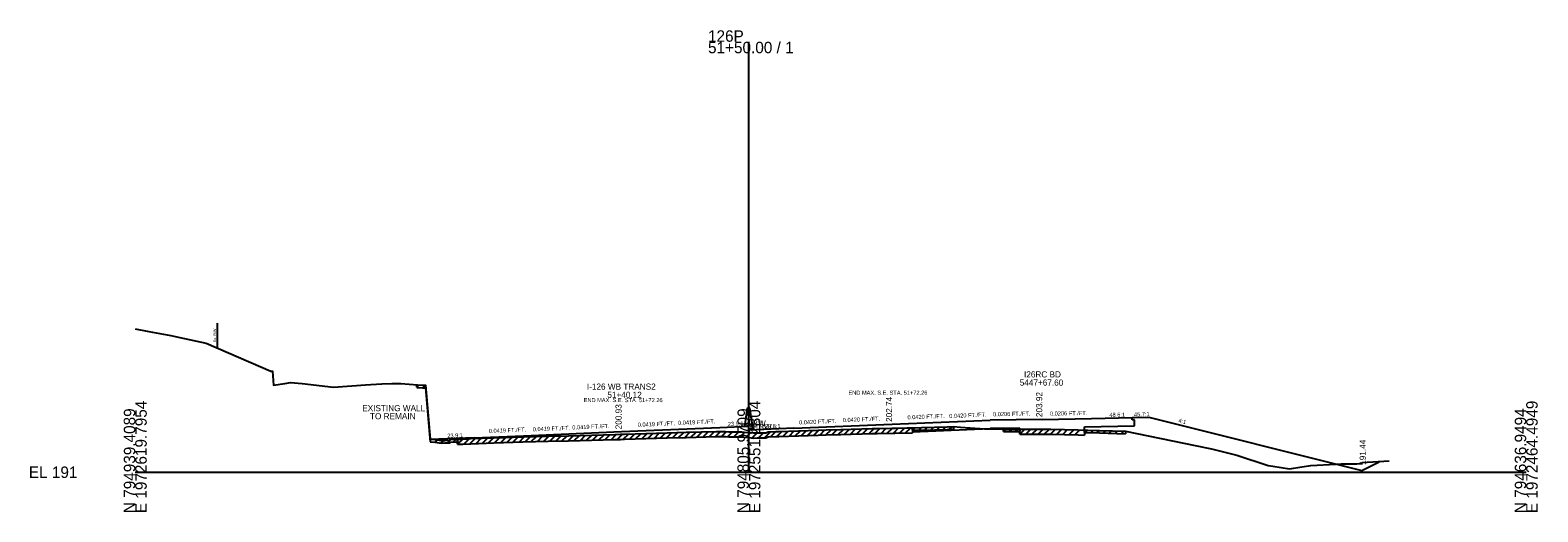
# Model space of a CAD drawing. Extents: x -161 to 1970889, y -4362 to 797231.
# Drawn here: x 1974.3 to 2342.8, y 3990.3 to 4108.1 of the extents above; entities that cross this region are included whole.
import ezdxf

# ---------------------------------------------------------------- set-up
doc = ezdxf.new("R2010")
doc.units = 0
for name, color, linetype in [('RD_GPK_XS_Cell', 7, 'Continuous'), ('RD_XS_Base', 7, 'Continuous'), ('RD_XS_EarthShd', 7, 'Continuous'), ('RD_XS_ExGround', 7, 'Continuous'), ('RD_XS_ExPaveRet', 7, 'Continuous'), ('RD_XS_ExRW', 7, 'Continuous'), ('RD_XS_MedBWall', 7, 'Continuous'), ('RD_XS_Misc_Line', 7, 'Continuous'), ('RD_XS_Pave', 7, 'Continuous'), ('RD_XS_PaveOvlay', 7, 'Continuous'), ('RD_XS_PaveShd', 7, 'Continuous'), ('RD_XS_TieSlope', 7, 'Continuous'), ('RD_XS_TX_Elev_EX', 7, 'Continuous'), ('RD_XS_TX_Elev_PR', 7, 'Continuous'), ('RD_XS_TX_Misc', 7, 'Continuous'), ('RD_XS_TX_MkPT', 7, 'Continuous'), ('RD_XS_TX_Notes', 7, 'Continuous'), ('RD_XS_TX_Profile', 7, 'Continuous'), ('RD_XS_TX_ShdSlope', 7, 'Continuous'), ('RD_XS_TX_Slope', 7, 'Continuous'), ('RD_XS_TX_Station', 7, 'Continuous')]:
    doc.layers.add(name, color=color, linetype=linetype)

msp = doc.modelspace()

# ---------------------------------------------------------------- linework, layer by layer
at = {"layer": 'RD_GPK_XS_Cell'}
for p, q in [((2150, 4000), (2150, 4105.24)), ((2000, 4000), (2150, 4000)), ((2150, 4000), (2340, 4000))]:
    msp.add_line(p, q, dxfattribs=at)
at = {"layer": 'RD_XS_Base'}
for p, q in [((2243.71, 4012.81), (2243.71, 4013.37)), ((2190.02, 4009.91), (2209, 4010.71)), ((2216.19, 4010.8), (2209, 4010.71)), ((2232.05, 4011.09), (2244.21, 4011.34)), ((2244.21, 4012.82), (2243.71, 4012.81)), ((2244.21, 4011.34), (2244.21, 4012.82))]:
    msp.add_line(p, q, dxfattribs=at)
at = {"layer": 'RD_XS_EarthShd'}
msp.add_line((2243.71, 4013.37), (2247.72, 4013.46), dxfattribs=at)
at = {"layer": 'RD_XS_ExGround'}
msp.add_line((2306.53, 4002.71), (2299.85, 4002.33), dxfattribs=at)
msp.add_lwpolyline([(2000, 4035.08), (2003.32, 4034.41), (2008.67, 4033.4), (2010.9, 4032.92), (2017.34, 4031.59), (2030.67, 4025.76), (2033.16, 4024.69), (2033.54, 4024.69), (2033.77, 4021.28), (2036.55, 4021.69), (2037.94, 4021.9), (2040.76, 4021.65), (2048.47, 4020.83), (2056.26, 4021.35), (2060.27, 4021.61), (2062.73, 4021.71), (2064.88, 4021.73), (2068.98, 4021.37), (2070.21, 4021.28), (2070.97, 4021.28), (2072.09, 4008.08), (2073.25, 4007.96), (2074.87, 4007.77), (2075.65, 4007.79), (2076.87, 4007.82), (2077.14, 4008), (2080.07, 4008.12), (2082.04, 4008.21), (2087.62, 4008.41), (2094.77, 4008.67), (2100.95, 4008.81), (2105.87, 4008.93), (2117.23, 4009.23), (2118.59, 4009.27), (2119.62, 4009.29), (2130.04, 4009.62), (2134.69, 4009.76), (2141.98, 4009.97), (2143.34, 4009.98), (2144.27, 4009.97), (2145.07, 4009.86), (2147.8, 4009.89), (2148.3, 4009.9), (2148.81, 4009.83), (2150, 4009.71), (2151.13, 4009.6), (2151.99, 4009.62), (2154.17, 4009.65), (2154.72, 4009.86), (2156.54, 4009.95), (2157.27, 4009.99), (2166.96, 4010.29), (2168.88, 4010.35), (2172.45, 4010.46), (2180.12, 4010.69), (2181.38, 4010.72), (2192.19, 4010.94), (2198.49, 4011.1), (2200.02, 4011.14), (2201.69, 4011.03), (2207.56, 4010.59), (2210.13, 4010.6), (2212.19, 4010.55), (2214.94, 4010.55), (2215.95, 4010.55), (2217.48, 4010.55), (2223.83, 4010.53), (2230.49, 4010.36), (2232.85, 4010.3), (2235.72, 4010.22), (2242.06, 4010.04), (2259.1, 4006.5), (2263.06, 4005.68), (2269.24, 4004.18), (2276.94, 4001.63), (2278.08, 4001.46), (2282.15, 4000.83), (2285.18, 4001.3), (2287.35, 4001.64), (2293.43, 4001.93), (2294.8, 4002.02), (2298.57, 4002.07), (2300, 4002.09)], dxfattribs=at)
at = {"layer": 'RD_XS_ExPaveRet'}
for p, q in [((2068.8, 4020.76), (2068.8, 4021.38)), ((2068.8, 4020.76), (2068.98, 4020.74)), ((2068.98, 4020.74), (2070.21, 4020.66)), ((2070.21, 4020.66), (2070.97, 4020.66)), ((2070.97, 4020.66), (2072.09, 4007.46)), ((2181.38, 4009.47), (2190.02, 4009.64)), ((2190.02, 4010.89), (2190.02, 4009.64)), ((2190.02, 4010.27), (2190.02, 4010.89)), ((2190.02, 4010.27), (2192.19, 4010.31)), ((2192.19, 4010.31), (2198.49, 4010.48)), ((2198.49, 4010.48), (2200.02, 4010.52)), ((2200.02, 4011.14), (2200.02, 4010.52)), ((2212.19, 4009.92), (2212.19, 4010.55)), ((2212.19, 4009.92), (2214.94, 4009.93)), ((2214.94, 4009.93), (2215.95, 4009.93)), ((2215.95, 4009.93), (2216.19, 4009.93)), ((2216.19, 4009.3), (2216.19, 4010.55)), ((2216.19, 4010.55), (2216.19, 4009.93)), ((2232.05, 4010.32), (2232.05, 4009.07)), ((2232.05, 4009.7), (2232.05, 4010.32)), ((2232.05, 4009.7), (2232.85, 4009.68)), ((2232.85, 4009.68), (2235.72, 4009.6)), ((2242.06, 4010.04), (2242.06, 4009.41)), ((2072.09, 4007.46), (2073.25, 4007.33)), ((2073.25, 4007.33), (2074.87, 4007.14)), ((2074.87, 4007.14), (2075.65, 4007.17)), ((2075.65, 4007.17), (2076.87, 4007.19)), ((2076.87, 4007.19), (2077.14, 4007.37)), ((2077.14, 4007.37), (2078.8, 4007.44)), ((2078.8, 4006.82), (2078.8, 4008.07)), ((2078.8, 4008.07), (2078.8, 4007.44)), ((2078.8, 4006.82), (2080.07, 4006.87)), ((2080.07, 4006.87), (2082.04, 4006.96)), ((2082.04, 4006.96), (2087.62, 4007.16)), ((2087.62, 4007.16), (2094.77, 4007.42)), ((2094.77, 4007.42), (2100.95, 4007.56)), ((2100.95, 4007.56), (2105.87, 4007.68)), ((2105.87, 4007.68), (2117.23, 4007.98)), ((2117.23, 4007.98), (2118.59, 4008.02)), ((2118.59, 4008.02), (2119.62, 4008.04)), ((2119.62, 4008.04), (2130.04, 4008.37)), ((2130.04, 4008.37), (2134.69, 4008.51)), ((2134.69, 4008.51), (2141.98, 4008.72)), ((2141.98, 4008.72), (2143.34, 4008.73)), ((2143.34, 4008.73), (2144.27, 4008.72)), ((2144.27, 4008.72), (2145.07, 4008.61)), ((2145.07, 4008.61), (2147.8, 4008.64)), ((2147.8, 4008.64), (2148.3, 4008.65)), ((2148.3, 4008.65), (2148.81, 4008.58)), ((2148.81, 4008.58), (2150, 4008.46)), ((2150, 4008.46), (2151.13, 4008.35)), ((2151.13, 4008.35), (2151.99, 4008.37)), ((2151.99, 4008.37), (2154.17, 4008.4)), ((2154.17, 4008.4), (2154.72, 4008.61)), ((2154.72, 4008.61), (2156.54, 4008.7)), ((2156.54, 4008.7), (2157.27, 4008.74)), ((2157.27, 4008.74), (2166.96, 4009.04)), ((2166.96, 4009.04), (2168.88, 4009.1)), ((2168.88, 4009.1), (2172.45, 4009.21)), ((2172.45, 4009.21), (2180.12, 4009.44)), ((2180.12, 4009.44), (2181.38, 4009.47)), ((2216.19, 4009.3), (2217.48, 4009.3)), ((2217.48, 4009.3), (2223.83, 4009.28)), ((2223.83, 4009.28), (2230.49, 4009.11)), ((2230.49, 4009.11), (2232.05, 4009.07)), ((2235.72, 4009.6), (2242.06, 4009.41))]:
    msp.add_line(p, q, dxfattribs=at)
at = {"layer": 'RD_XS_ExRW'}
msp.add_line((2020, 4036.43), (2020, 4030.43), dxfattribs=at)
at = {"layer": 'RD_XS_MedBWall'}
for p, q in [((2149, 4011.2), (2149.67, 4015.74)), ((2150.19, 4015.74), (2149.67, 4015.74)), ((2151, 4010.31), (2150.19, 4015.74))]:
    msp.add_line(p, q, dxfattribs=at)
at = {"layer": 'RD_XS_Misc_Line'}
for p, q in [((2068.8, 4020.76), (2069.38, 4021.34)), ((2070.3, 4020.66), (2070.92, 4021.28)), ((2071.8, 4010.97), (2071.84, 4011.02)), ((2129.8, 4008.36), (2131.09, 4009.65)), ((2131.3, 4008.41), (2132.59, 4009.7)), ((2132.8, 4008.45), (2134.09, 4009.74)), ((2134.3, 4008.5), (2135.58, 4009.79)), ((2135.8, 4008.54), (2137.08, 4009.83)), ((2137.3, 4008.59), (2138.58, 4009.87)), ((2138.8, 4008.63), (2140.08, 4009.92)), ((2140.3, 4008.67), (2141.58, 4009.96)), ((2141.8, 4008.72), (2143.06, 4009.98)), ((2143.3, 4008.73), (2144.51, 4009.94)), ((2144.8, 4008.65), (2146.02, 4009.87)), ((2146.3, 4008.63), (2147.56, 4009.89)), ((2147.8, 4008.64), (2148.97, 4009.82)), ((2149.3, 4008.53), (2150.43, 4009.67)), ((2152.3, 4008.37), (2153.56, 4009.64)), ((2153.8, 4008.39), (2155.29, 4009.89)), ((2155.3, 4008.64), (2156.61, 4009.95)), ((2156.8, 4008.71), (2158.1, 4010.02)), ((2158.3, 4008.77), (2159.59, 4010.06)), ((2159.8, 4008.82), (2161.09, 4010.11)), ((2161.3, 4008.86), (2162.59, 4010.15)), ((2162.8, 4008.91), (2164.09, 4010.2)), ((2164.3, 4008.96), (2165.59, 4010.25)), ((2165.8, 4009), (2167.09, 4010.29)), ((2167.3, 4009.05), (2168.59, 4010.34)), ((2168.8, 4009.1), (2170.09, 4010.39)), ((2170.3, 4009.14), (2171.59, 4010.43)), ((2171.8, 4009.19), (2173.09, 4010.48)), ((2173.3, 4009.24), (2174.59, 4010.52)), ((2174.8, 4009.28), (2176.09, 4010.57)), ((2176.3, 4009.33), (2177.59, 4010.62)), ((2177.8, 4009.37), (2179.09, 4010.66)), ((2179.3, 4009.42), (2180.58, 4010.7)), ((2180.8, 4009.46), (2182.07, 4010.73)), ((2182.3, 4009.48), (2183.57, 4010.76)), ((2183.8, 4009.52), (2185.07, 4010.79)), ((2185.3, 4009.55), (2186.57, 4010.82)), ((2186.8, 4009.58), (2188.07, 4010.85)), ((2188.3, 4009.61), (2189.57, 4010.88)), ((2190.02, 4010.27), (2190.66, 4010.91)), ((2191.52, 4010.3), (2192.16, 4010.94)), ((2193.02, 4010.33), (2193.66, 4010.98)), ((2194.52, 4010.37), (2195.16, 4011.02)), ((2196.02, 4010.41), (2196.66, 4011.06)), ((2197.52, 4010.45), (2198.16, 4011.1)), ((2199.02, 4010.49), (2199.66, 4011.13)), ((2212.19, 4009.92), (2212.82, 4010.55)), ((2213.69, 4009.93), (2214.32, 4010.55)), ((2215.19, 4009.93), (2215.82, 4010.55)), ((2216.19, 4009.3), (2217.44, 4010.55)), ((2217.69, 4009.3), (2218.94, 4010.54)), ((2219.19, 4009.29), (2220.44, 4010.54)), ((2220.69, 4009.29), (2221.94, 4010.53)), ((2222.19, 4009.28), (2223.44, 4010.53)), ((2223.69, 4009.28), (2224.92, 4010.5)), ((2225.2, 4009.24), (2226.41, 4010.46)), ((2226.7, 4009.2), (2227.91, 4010.42)), ((2228.2, 4009.17), (2229.41, 4010.39)), ((2229.7, 4009.13), (2230.91, 4010.35)), ((2232.05, 4009.7), (2232.66, 4010.31)), ((2233.55, 4009.66), (2234.16, 4010.27)), ((2235.05, 4009.62), (2235.66, 4010.22)), ((2236.55, 4009.57), (2237.16, 4010.18)), ((2238.05, 4009.53), (2238.66, 4010.14)), ((2239.55, 4009.48), (2240.16, 4010.09)), ((2241.05, 4009.44), (2241.66, 4010.05)), ((2073.3, 4007.33), (2073.85, 4007.89)), ((2074.8, 4007.15), (2075.43, 4007.78)), ((2076.3, 4007.18), (2077.05, 4007.94)), ((2077.8, 4007.4), (2078.45, 4008.05)), ((2078.8, 4006.82), (2080.1, 4008.12)), ((2080.3, 4006.88), (2081.61, 4008.19)), ((2081.8, 4006.95), (2083.09, 4008.25)), ((2083.3, 4007.01), (2084.59, 4008.3)), ((2084.8, 4007.06), (2086.09, 4008.35)), ((2086.3, 4007.11), (2087.59, 4008.4)), ((2087.8, 4007.16), (2089.09, 4008.46)), ((2089.3, 4007.22), (2090.59, 4008.51)), ((2090.8, 4007.27), (2092.09, 4008.57)), ((2092.3, 4007.33), (2093.59, 4008.62)), ((2093.8, 4007.38), (2095.09, 4008.68)), ((2095.3, 4007.43), (2096.58, 4008.71)), ((2096.8, 4007.47), (2098.08, 4008.75)), ((2098.3, 4007.5), (2099.58, 4008.78)), ((2099.8, 4007.54), (2101.08, 4008.82)), ((2101.3, 4007.57), (2102.58, 4008.85)), ((2102.8, 4007.61), (2104.08, 4008.89)), ((2104.3, 4007.64), (2105.58, 4008.92)), ((2105.8, 4007.68), (2107.08, 4008.96)), ((2107.3, 4007.72), (2108.58, 4009)), ((2108.8, 4007.76), (2110.08, 4009.04)), ((2110.3, 4007.8), (2111.58, 4009.08)), ((2111.8, 4007.84), (2113.08, 4009.12)), ((2113.3, 4007.88), (2114.58, 4009.16)), ((2114.8, 4007.91), (2116.08, 4009.2)), ((2116.3, 4007.95), (2117.58, 4009.24)), ((2117.8, 4007.99), (2119.08, 4009.28)), ((2119.3, 4008.04), (2120.59, 4009.32)), ((2120.8, 4008.08), (2122.09, 4009.37)), ((2122.3, 4008.13), (2123.59, 4009.42)), ((2123.8, 4008.17), (2125.09, 4009.46)), ((2125.3, 4008.22), (2126.59, 4009.51)), ((2126.8, 4008.27), (2128.09, 4009.56)), ((2128.3, 4008.31), (2129.59, 4009.6)), ((2150.8, 4008.39), (2152.03, 4009.62))]:
    msp.add_line(p, q, dxfattribs=at)
at = {"layer": 'RD_XS_Pave'}
for p, q in [((2094.88, 4008.93), (2118.88, 4009.93)), ((2118.88, 4009.93), (2142.88, 4010.94)), ((2161, 4010.73), (2185, 4011.74)), ((2185, 4011.74), (2209, 4012.75)), ((2221.7, 4012.92), (2209, 4012.75)), ((2221.7, 4012.92), (2233.71, 4013.16)), ((2082.88, 4008.42), (2094.88, 4008.93))]:
    msp.add_line(p, q, dxfattribs=at)
at = {"layer": 'RD_XS_PaveOvlay'}
for p, q in [((2130.04, 4009.62), (2134.69, 4009.76)), ((2134.69, 4009.76), (2141.98, 4009.97)), ((2141.98, 4009.97), (2143.34, 4009.98)), ((2143.34, 4009.98), (2144.27, 4009.97)), ((2144.27, 4009.97), (2145.07, 4009.86)), ((2145.07, 4009.86), (2147.8, 4009.89)), ((2147.8, 4009.89), (2148.3, 4009.9)), ((2148.3, 4009.9), (2148.81, 4009.83)), ((2148.81, 4009.83), (2150, 4009.71)), ((2150, 4009.71), (2151.13, 4009.6)), ((2151.99, 4009.62), (2154.17, 4009.65)), ((2154.17, 4009.65), (2154.72, 4009.86)), ((2154.72, 4009.86), (2156.54, 4009.95)), ((2156.54, 4009.95), (2157.27, 4009.99)), ((2157.27, 4009.99), (2166.96, 4010.29)), ((2166.96, 4010.29), (2168.88, 4010.35)), ((2168.88, 4010.35), (2172.45, 4010.46)), ((2172.45, 4010.46), (2180.12, 4010.69)), ((2180.12, 4010.69), (2181.38, 4010.72)), ((2181.38, 4010.72), (2190.02, 4010.89)), ((2190.02, 4010.89), (2190.02, 4009.91)), ((2216.19, 4010.55), (2216.19, 4010.8)), ((2216.19, 4010.55), (2220.65, 4010.54)), ((2220.65, 4010.54), (2223.83, 4010.53)), ((2223.83, 4010.53), (2227.16, 4010.44)), ((2227.16, 4010.44), (2230.49, 4010.36)), ((2230.49, 4010.36), (2232.05, 4010.32)), ((2232.05, 4010.32), (2232.05, 4011.09)), ((2072.09, 4008.08), (2072.1, 4007.97)), ((2078.8, 4008.07), (2080.07, 4008.12)), ((2080.07, 4008.12), (2082.04, 4008.21)), ((2082.04, 4008.21), (2087.62, 4008.41)), ((2087.62, 4008.41), (2094.77, 4008.67)), ((2094.77, 4008.67), (2100.95, 4008.81)), ((2100.95, 4008.81), (2105.87, 4008.93)), ((2105.87, 4008.93), (2117.23, 4009.23)), ((2117.23, 4009.23), (2118.59, 4009.27)), ((2118.59, 4009.27), (2119.62, 4009.29)), ((2119.62, 4009.29), (2130.04, 4009.62)), ((2151.13, 4009.6), (2151.99, 4009.62))]:
    msp.add_line(p, q, dxfattribs=at)
msp.add_lwpolyline([(2072.09, 4008.08), (2073.25, 4007.96), (2074.87, 4007.77), (2075.65, 4007.79), (2076.87, 4007.82), (2077.14, 4008), (2078.8, 4008.07)], dxfattribs=at)
at = {"layer": 'RD_XS_PaveShd'}
for p, q in [((2233.71, 4013.16), (2243.71, 4013.37)), ((2142.88, 4010.94), (2150, 4011.24)), ((2150, 4010.27), (2150, 4011.24)), ((2161, 4010.73), (2150, 4010.27)), ((2082.88, 4008.42), (2072.1, 4007.97))]:
    msp.add_line(p, q, dxfattribs=at)
at = {"layer": 'RD_XS_TieSlope'}
for p, q in [((2247.72, 4013.46), (2299.81, 4000.44)), ((2299.81, 4000.44), (2304.08, 4002.57))]:
    msp.add_line(p, q, dxfattribs=at)

# ---------------------------------------------------------------- texts
at = {"layer": 'RD_GPK_XS_Cell'}
for s, p in [('126P', (2140, 4105.24)), ('51+50.00 / 1', (2140, 4102.44)), ('EL 191', (1974, 3998.6))]:
    msp.add_text(s, height=2.8, dxfattribs=at).set_placement(p)
for s, p in [('E 1972619.7954', (2002.8, 3990)), ('E 1972551.2804', (2152.8, 3990)), ('E 1972464.4949', (2342.8, 3990)), ('N 794939.4089', (2000, 3990)), ('N 794805.9709', (2150, 3990)), ('N 794636.9494', (2340, 3990))]:
    msp.add_text(s, height=2.8, rotation=90, dxfattribs=at).set_placement(p)
at = {"layer": 'RD_XS_ExRW'}
msp.add_text('Ex. R/W ', height=0.65, rotation=90, dxfattribs=at).set_placement((2019.75, 4031.81))
at = {"layer": 'RD_XS_TX_Elev_EX'}
msp.add_text('200.71', height=1, rotation=90, dxfattribs=at).set_placement((2151, 4009.71))
at = {"layer": 'RD_XS_TX_Elev_PR'}
for s, p in [(' 202.74', (2185, 4011.74)), (' 203.92', (2221.7, 4012.92)), (' 200.93', (2118.88, 4009.93))]:
    msp.add_text(s, height=1.5, rotation=90, dxfattribs=at).set_placement(p)
at = {"layer": 'RD_XS_TX_Misc'}
msp.add_text('191.44', height=1.5, rotation=90, dxfattribs=at).set_placement((2300.78, 4001.81))
at = {"layer": 'RD_XS_TX_MkPT'}
for s, p in [('WBW', (2149, 4011.2)), ('EBW', (2151, 4010.31))]:
    msp.add_text(s, height=1.5, dxfattribs=at).set_placement(p)
at = {"layer": 'RD_XS_TX_Notes'}
for s, height, p in [('END MAX. S.E. STA. 51+72.26', 1, (2109.6, 4017.13)), ('END MAX. S.E. STA. 51+72.26', 1, (2174.33, 4018.94)), ('EXISTING WALL', 1.5, (2055.48, 4014.92)), ('TO REMAIN', 1.5, (2057.37, 4012.95))]:
    msp.add_text(s, height=height, dxfattribs=at).set_placement(p)
at = {"layer": 'RD_XS_TX_Profile'}
for s, rotation, p in [('48.6:1', 1.1782, (2238.12, 4013.51)), ('23.9:1', 2.4001, (2144.85, 4011.27)), ('23.8:1', 2.405, (2153.91, 4010.68)), ('23.9:1', 2.4, (2076.29, 4008.4))]:
    msp.add_text(s, height=1, rotation=rotation, dxfattribs=at).set_placement(p)
at = {"layer": 'RD_XS_TX_ShdSlope'}
msp.add_text('45.7:1', height=1, rotation=1.2522, dxfattribs=at).set_placement((2244.13, 4013.63))
at = {"layer": 'RD_XS_TX_Slope'}
for s, rotation, p in [('0.0420 FT./FT.', 2.405, (2172.96, 4012.23)), ('0.0420 FT./FT.', 2.405, (2188.77, 4012.9)), ('0.0420 FT./FT.', 2.405, (2198.98, 4013.23)), ('0.0206 FT./FT.', 1.1784, (2209.68, 4013.67)), ('0.0206 FT./FT.', 1.1784, (2223.59, 4013.82)), ('0.0419 FT./FT.', 2.4001, (2086.43, 4009.58)), ('0.0419 FT./FT.', 2.4001, (2097.18, 4009.99)), ('0.0419 FT./FT.', 2.4, (2106.84, 4010.43)), ('0.0419 FT./FT.', 2.4001, (2122.84, 4011.1)), ('0.0419 FT./FT.', 2.4001, (2132.69, 4011.56)), ('0.0420 FT./FT.', 2.405, (2162.28, 4011.66)), ('4:1', 344.1175, (2254.9, 4012.24))]:
    msp.add_text(s, height=1, rotation=rotation, dxfattribs=at).set_placement(p)
at = {"layer": 'RD_XS_TX_Station'}
for s, p in [('I26RC BD', (2217.24, 4023.17)), ('I-126 WB TRANS2', (2110.39, 4020.18)), ('5447+67.60', (2216.19, 4021.17)), ('51+40.12', (2115.39, 4018.18))]:
    msp.add_text(s, height=1.5, dxfattribs=at).set_placement(p)

doc.saveas('drawing.dxf')
